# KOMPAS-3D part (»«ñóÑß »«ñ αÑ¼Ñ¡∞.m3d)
File: created 26.10.2015 15:31:09, last saved 28.10.2015 10:20:14.
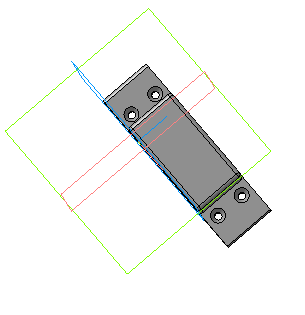
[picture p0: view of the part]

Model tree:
1. Эскиз:1
2. Операция выдавливания:1
     Расстояние 1 = 15
3. Эскиз:2
4. Вырезать элемент выдавливания:1
     Расстояние 1 = 20
5. Эскиз:3
6. Вырезать элемент выдавливания:2
     Расстояние 1 = 20
7. Эскиз:4
8. Вырезать элемент выдавливания:3
     Расстояние 1 = 3; Угол 1 = 27
9. Скругление:1
     Радиус = 1
10. Скругление:2
     Радиус = 1
11. Скругление:3
     Радиус = 1
12. Скругление:4
     Радиус = 1
13. Скругление:5
     Радиус = 1
14. Скругление:6
     Радиус = 1
15. Скругление:7
     Радиус = 1
16. Скругление:8
     Радиус = 1
17. Эскиз:5
18. Вырезать элемент выдавливания:4
     Расстояние 1 = 43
